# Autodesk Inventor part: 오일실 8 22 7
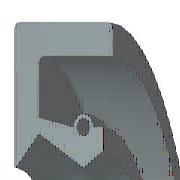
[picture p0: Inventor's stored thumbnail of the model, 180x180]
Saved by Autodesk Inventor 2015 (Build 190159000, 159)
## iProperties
IsCustomPart: 1
Created: 2012-02
Part Number: 오일실 8 22 7
Material: 고무
Description: 오일-실
Document SubType Name: Modeling
Standard: KS B 2804
Designer: mduedu
Standards Organization: KS
Language: ko-KR
Size Designation: D - 8 22 7
Categories: <MemberInstance><Categories><Category DisplayName="샤프트 부품" InternalName="7f7aeb1f-a693-4053-b835-cee3144e0d98" Mnemonic="SHFT"><Category DisplayName="실링" Intern
Density: 0.93 g/cm^3
Appearance: Rubber - Black - Version 1.1
Author: mduedu
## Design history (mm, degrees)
revolve "본체" stored, may be unused: angle "d17" = 90 deg
revolve "스프링1" stored, may be unused: angle "d18" = 90 deg
body "Solid1"
sketch "스케치1"
  geometry: L1 (0, 11)-(7, 11); L2 (7, 9.25)-(1.75, 9.25); L3 (1.75, 5.75)-(4.9, 4); L4 (4.9, 4)-(0, 4); L5 (0, 0)-(9.586, 0) reference; L6 (4.9, 4)-(6.3, 4.875); L7 (0, 18)-(0, -3) reference; L8 (-1.941, 0)-(11.507, 0) reference; L9 (4.2, 6.1)-(1.75, 6.59); L10 (1.75, 6.59)-(1.75, 9.25); L11 (0, 11)-(0, 4.088); L12 (4.9, 4)-(0, 4); L13 (1.75, 5.75)-(0.152, 4.028); L14 (7, 11)-(7, 9.25); L15 (5.6, 6.1)-(6.3, 6.1); L16 (6.3, 6.1)-(6.3, 4.875); C1 r 0.455 at (4.9, 6.1); A1 r 0.7 centre (4.9, 6.1) between (5.6, 6.1) and (4.2, 6.1); A2 r 0.088 centre (0.088, 4.088) between (0, 4.088) and (0.152, 4.028); 1 further point
  constraints: 28 end point, 5 horizontal alignment, 5 point on line, 4 point on circle, 4 vertical alignment, 3 centre point, 3 tangent, 2 collinear, 2 horizontal, 2 perpendicular, 1 coincident, 1 parallel
  dimensions: "d0" = 22 diameter of L1 L5 (= SD2); "d1" = 1.75 distance of L1.end L2.start (= SD); "d2" = 0.91 diameter of C1 (= SPDI); "d3" = 1.4 diameter of A1 (= SPDA); "d4" = 8 diameter of L3.end L5 (= NND); "d5" = 11.5 diameter of L3.start L5 (= TKDM); "d7" = 13.18 diameter of L9.end L5 (= TKDM + 0.24 x SWDT); "d8" = 1.75 distance between parallel lines of L11 L10 (= SD); "d9" = 4.9 distance from line of L11 C1.centre (= SPDST); "d10" = 12.2 diameter of C1.centre L5 (= HLDM); "d11" = 0.0875 radius of A2 (= 0.25 x LAB); "d12" = 6.3 distance between parallel lines of L11 L16 (= SDI); "d13" = 9.75 diameter of L6.end L5 (= ABDM); "d14" = 7 distance from line of L11 L1.end (= SWDT)
fillet "모깎기1" dims "d6" = 0.3 (= RR)
other parameters: "SD2" = 22 [user parameter; used in 1 equation term], "SWDT" = 7 [user parameter; used in 2 equation terms], "RR" = 0.3 [user parameter; used in 1 equation term], "SD" = 1.75 [user parameter; used in 2 equation terms], "NND" = 8 [user parameter; used in 1 equation term], "SPDA" = 1.4 [user parameter; used in 1 equation term], "SPDI" = 0.91 [user parameter; used in 1 equation term], "TKDM" = 11.5 [user parameter; used in 2 equation terms], "HLDM" = 12.2 [user parameter; used in 1 equation term], "ABDM" = 9.75 [user parameter; used in 1 equation term], "SDI" = 6.3 [user parameter; used in 1 equation term], "SPDST" = 4.9 [user parameter; used in 1 equation term], "LAB" = 0.35 [user parameter; used in 1 equation term], "d15" = 0, "d16" = 0, "d19" = 0
